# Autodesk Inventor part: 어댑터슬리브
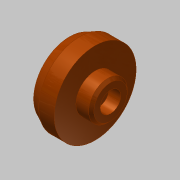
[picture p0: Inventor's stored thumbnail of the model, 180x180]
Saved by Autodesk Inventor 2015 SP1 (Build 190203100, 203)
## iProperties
Created: 2016-06
Part Number: 어댑터슬리브
Material: 강철, 탄소
Document SubType Name: Modeling
Designer: mduedu
Density: 7.87 g/cm^3
Appearance: 매끄러움 - 연한 주황색
Author: mduedu
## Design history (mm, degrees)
sketch "스케치2"
  geometry: L1 (0, 0)-(0, 14); L2 (0, 14)-(-4, 16); L3 (-4, 16)-(-10, 16); L4 (-10, 16)-(-10, 7.5); L5 (-10, 7.5)-(-16, 7.5); L6 (-16, 7.5)-(-16, 0); L7 (-16, 0)-(0, 0)
  constraints: 14 end point, 4 parallel, 1 perpendicular, 1 vertical
  dimensions: "d0" = 32 diameter of L3 L7; "d2" = 28 diameter of L1.end L7; "d3" = 6 distance of L2.end L3.end; "d4" = 6 distance of L4.end L5.end; "d5" = 15 diameter of L5 L7; "d6" = 16 distance between parallel lines of L6 L1
revolve "회전1" sketch "스케치2" stored, may be unused: angle "d7" = 90 deg
sketch "스케치3"
  geometry: L1 (-16, -7.5)-(-16, 7.5) reference; L2 (-16, 7.5)-(-10, 7.5) reference; L3 (-10, 7.5)-(-10, 16) reference; L4 (-10, 16)-(-4, 16) reference; L5 (-4, 16)-(0, 14) reference; L6 (0, 14)-(0, -14) reference; L7 (0, -14)-(-4, -16) reference; L8 (-4, -16)-(-10, -16) reference; L9 (-10, -16)-(-10, -7.5) reference; L10 (-10, -7.5)-(-16, -7.5) reference; L11 (0, 10)-(-5, 10); L12 (-5, 10)-(-5, 8); L13 (-5, 8)-(-7, 6); L14 (-7, 6)-(-7, 0); L15 (-7, 0)-(0, 0); L16 (0, 10)-(0, 0)
  constraints: 12 end point, 3 parallel, 2 perpendicular, 1 point on line
  dimensions: "d8" = 20 diameter of L11 L15; "d10" = 16 diameter of L12.end L15; "d11" = 12 diameter of L13.end L15; "d12" = 9 distance between parallel lines of L14 L1; "d13" = 2 distance between parallel lines of L12 L14
revolve "회전2" sketch "스케치3" stored, may be unused: angle "d14" = 90 deg
chamfer "모따기1" distance "d15" = 1; stored, may be unused: second distance "d16" = 2, angle "d17" = 45 deg
sketch "스케치4"
  geometry: 2 further points
  constraints: 1 coincident
sketch "스케치5"
  geometry: 1 further point
hole "구멍1" sketch "스케치5" at (0, 0) diameter "d18" = 4.5; stored, may be unused: countersink angle "d22" = 90 deg, drill point angle "d24" = 0 deg; dims "d19" = 6, "d20" = 8, "d21" = 4.6, "d23" = 8
node "솔리드1"
node "절단 모서리 투영1"
